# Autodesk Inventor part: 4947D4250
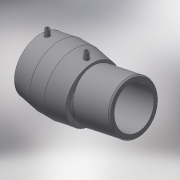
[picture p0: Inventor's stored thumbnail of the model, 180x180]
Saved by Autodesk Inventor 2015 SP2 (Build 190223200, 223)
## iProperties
Created: 2017-06
Part Number: 4947D4250
Material: Generic
Description: PLASSON ADJUSTABLE ELBOW (ONE SIDE) 250
Document SubType Name: Modeling
Designer: KIM
Mass: 10909.3 g
Surface Area: 8060.11 cm^2
Volume: 10909.3 cm^3
Density: 1 g/cm^3
Appearance: Default
Author: KIM
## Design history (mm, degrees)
derived "4947D4.ipt"
feature "Solid1::4947D4.ipt"
tag "TaggingFeature1"
body "Solid1"
other parameters: "d0" = 238.875, "d2" = 312, "d3" = 123, "d4" = 61.5, "d5" = 280.8, "d8" = 168 deg, "d10" = 49.2, "d11" = 16.4, "d29" = 156, "d30" = 15, "d31" = 91, "d34" = 5 deg, "d41" = 4, "d42" = 14, "d43" = 0, "d48" = 225, "d55" = 69.525, "d57" = 168 deg, "d62" = 3, "d63" = 0, "d65" = 455, "d67" = 225, "d68" = 135 deg, "d69" = 134, "d70" = 115.44, "d71" = 6.24, "L_" = 455, "L_1" = 123, "D_" = 312, "A_" = 156, "d_2" = 12, "L_0" = 148, "L_2" = 134, "d54" = 115.875, "d59" = 285.77957
